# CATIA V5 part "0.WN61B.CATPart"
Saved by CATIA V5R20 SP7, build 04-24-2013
Part number: 0.WN61B
Material "Nessuno"
Bounding box of the stored display mesh (mm): x 0 to 149.213, y -135.185 to 0, z -56.919 to 41.584
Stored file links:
  C:\Users\designer2\Desktop\Ottobre 2022\25-10-2022\04\Yori Evo 48V\0.WN61B.CATPart
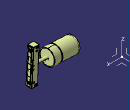
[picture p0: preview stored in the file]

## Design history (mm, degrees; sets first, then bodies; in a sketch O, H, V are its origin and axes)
AxisSystem1: origin (0, 0, 0), X (1, 0, 0), Y (0, 1, 0), Z (0, 0, 1)
Set1
  DatumSurface1
Body1 (main body), material "Nessuno"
